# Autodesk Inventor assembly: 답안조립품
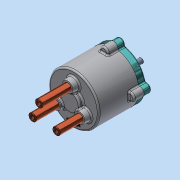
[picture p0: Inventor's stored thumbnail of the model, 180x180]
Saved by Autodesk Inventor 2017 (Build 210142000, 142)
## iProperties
Part Number: 답안조립품
Material: 일반
Document SubType Name: Assembly
Designer: MRC
Author: MRC
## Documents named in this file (14)
- C:\Users\MRC\Desktop\610708V1014\답안조립품.iam
- C:\Users\MRC\Desktop\610708V1014\본체.ipt
- C:\Users\MRC\Desktop\610708V1014\멈춤링 10 x 1.ipt
- C:\Users\MRC\Desktop\610708V1014\멈춤링 22 x 1.2.ipt
- C:\Users\MRC\Desktop\610708V1014\메인 축.ipt
- C:\Users\MRC\Desktop\610708V1014\베어링 NA 4900.ipt
- C:\Users\MRC\Desktop\610708V1014\볼트 M5.ipt
- C:\Users\MRC\Desktop\610708V1014\슬라이드 축.ipt
- C:\Users\MRC\Desktop\610708V1014\오일실.ipt
- C:\Users\MRC\Desktop\610708V1014\커버.ipt
- C:\Users\MRC\Desktop\610708V1014\판캠.ipt
- C:\Users\MRC\Desktop\610708V1014\가변스프링.ipt
- C:\Users\MRC\Desktop\610708V1014\가변스프링2.ipt
- C:\Users\MRC\Desktop\610708V1014\가변스프링3.ipt
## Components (3 placed, 3 different names)
1. 가변스프링:3
2. 가변스프링2:1
3. 가변스프링3:1
